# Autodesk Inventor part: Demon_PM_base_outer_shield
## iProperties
Shininess: 64.0
Length Units: 11269
Angle Units: 11279
Time Units: 11290
Mass Units: 11283
Length Display Precision: 3
Angle Display Precision: 2
Compacted: True
Part Number: Demon_PM_base_outer_shield
Document SubType Name: Modeling
Created: 2005-04
Material: Aluminum-6061
Designer: John Blackburn
Manufacturer: Standard
Standards Organization: Custom
Density: 0.0
Volumn: 0.0
Area: 0.0
PropertySet Name: Model Information
Control State: 0
Master: False
Checked Out: False
Author: John Blackburn
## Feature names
1. Extrusion1
2. Extrusion2
3. Extrusion3
4. Circular Pattern1
